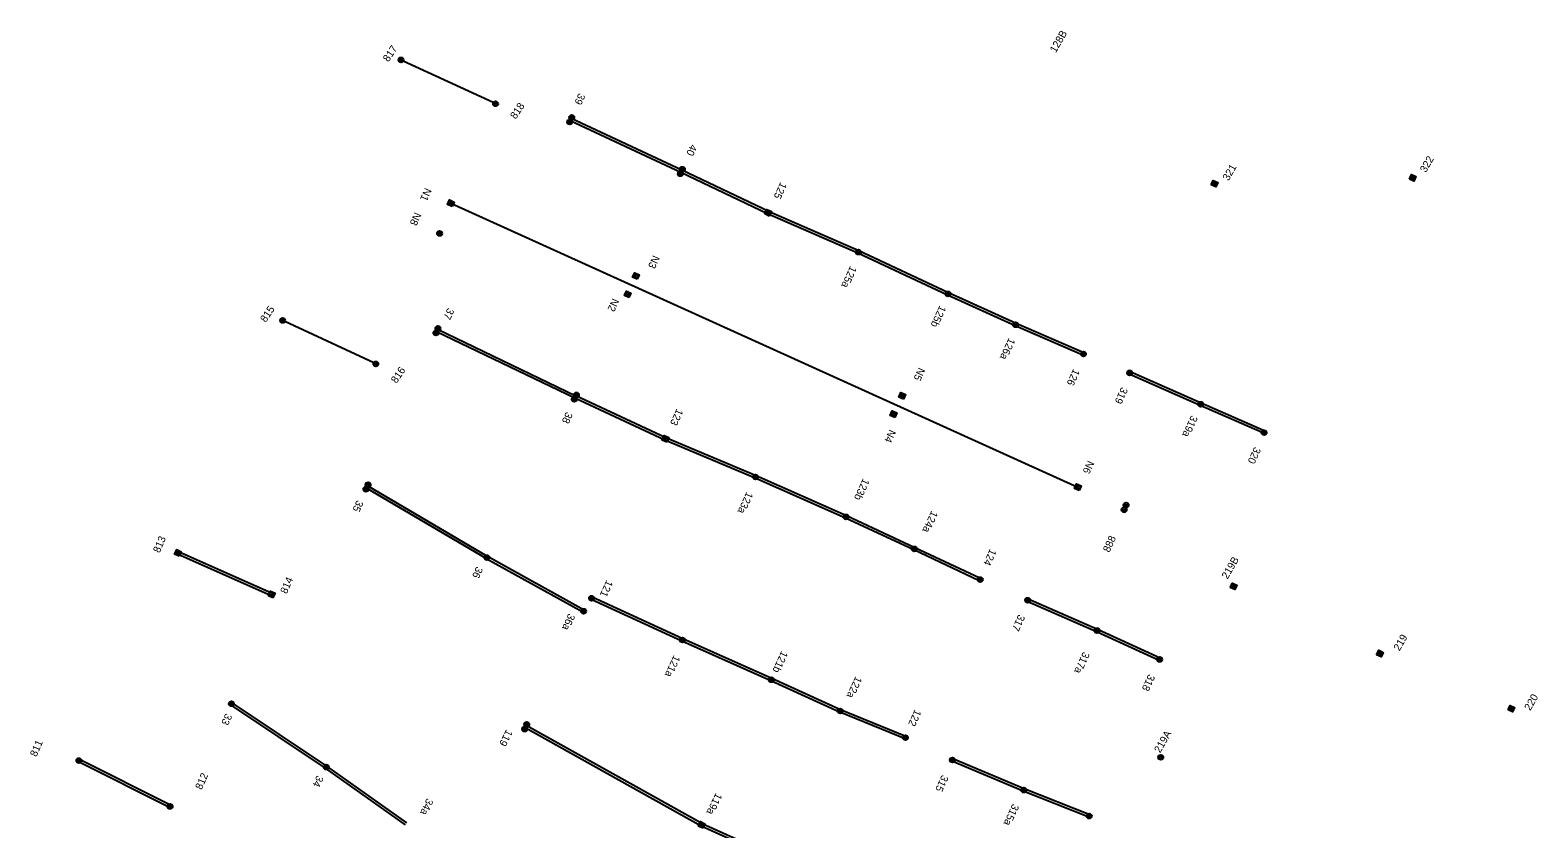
# Model space of a CAD drawing. Extents: x -595867 to -593796, y -1159595 to -1157495.
# Drawn here: x -595245.9 to -594943.7, y -1159060 to -1158899.8 of the extents above; entities that cross this region are included whole.
import ezdxf

# ---------------------------------------------------------------- set-up
doc = ezdxf.new("R2010")
doc.units = 0
for name, color, linetype in [('BVK_kanalizace_jednotna_nova', 7, 'Continuous'), ('DKM19', 7, 'Continuous'), ('SO31_06_54_1-protlak', 7, 'Continuous'), ('Vrstva 2', 7, 'Continuous'), ('Vrstva 7 návěstidla', 7, 'Continuous')]:
    doc.layers.add(name, color=color, linetype=linetype)

# ---------------------------------------------------------------- blocks, each defined once
blk = doc.blocks.new('C661_2')
at = {"layer": 'SO31_06_54_1-protlak'}
for p, q in [((-0.005, 0.0003), (-0.0003, 0.005)), ((-0.005, -0.005), (0.005, 0.005)), ((0.0003, -0.005), (0.005, -0.0003))]:
    blk.add_line(p, q, dxfattribs=at)
blk.add_lwpolyline([(-0.005, 0.005), (0.005, 0.005), (0.005, -0.005), (-0.005, -0.005)], close=True, dxfattribs=at)
blk.add_lwpolyline([(-0.005, 0.005), (0.005, 0.005), (0.005, -0.005), (-0.005, -0.005), (-0.005, 0.005)], dxfattribs=at)
blk = doc.blocks.new('C661')
at = {"layer": 'Vrstva 2'}
for p, q in [((-0.005, 0.0003), (-0.0003, 0.005)), ((-0.005, -0.005), (0.005, 0.005)), ((0.0003, -0.005), (0.005, -0.0003))]:
    blk.add_line(p, q, dxfattribs=at)
blk.add_lwpolyline([(-0.005, 0.005), (0.005, 0.005), (0.005, -0.005), (-0.005, -0.005)], close=True, dxfattribs=at)
blk.add_lwpolyline([(-0.005, 0.005), (0.005, 0.005), (0.005, -0.005), (-0.005, -0.005), (-0.005, 0.005)], dxfattribs=at)

msp = doc.modelspace()

# ---------------------------------------------------------------- linework, layer by layer
at = {"layer": 'BVK_kanalizace_jednotna_nova'}
for p, q in [((-595171.67, -1158906.23), (-595171.8, -1158905.33)), ((-595171.3, -1158906.18), (-595171.43, -1158905.27)), ((-595152.73, -1158915.04), (-595152.86, -1158914.14)), ((-595152.35, -1158914.99), (-595152.49, -1158914.08)), ((-595137.84, -1158918.69), (-595138, -1158917.79)), ((-595137.47, -1158918.64), (-595137.64, -1158917.72)), ((-595137.42, -1158917.78), (-595137.58, -1158916.88)), ((-595137.05, -1158917.73), (-595137.21, -1158916.81)), ((-595115.3, -1158929.02), (-595115.46, -1158928.11)), ((-595115.25, -1158928.16), (-595115.41, -1158927.26)), ((-595114.88, -1158928.1), (-595115.05, -1158927.19)), ((-595115.67, -1158929.08), (-595115.83, -1158928.18)), ((-595161.37, -1158934.05), (-595162, -1158934.28)), ((-595160.9, -1158934.27), (-595162.22, -1158934.76)), ((-595161.12, -1158934.75), (-595161.74, -1158934.98)), ((-595097.29, -1158936.17), (-595098.63, -1158936.63)), ((-595097.77, -1158935.94), (-595098.4, -1158936.16)), ((-595097.52, -1158936.65), (-595098.15, -1158936.86)), ((-595163.92, -1158941.03), (-595164.08, -1158940.13)), ((-595163.55, -1158940.97), (-595163.71, -1158940.06)), ((-595079.98, -1158944.79), (-595080.14, -1158943.89)), ((-595079.61, -1158944.73), (-595079.78, -1158943.82)), ((-595123.8, -1158948.86), (-595125.12, -1158949.34)), ((-595124.27, -1158948.64), (-595124.9, -1158948.86)), ((-595124.02, -1158949.34), (-595124.64, -1158949.57)), ((-595062.01, -1158953.16), (-595062.17, -1158952.26)), ((-595061.64, -1158953.1), (-595061.81, -1158952.19)), ((-595125.46, -1158952.51), (-595126.77, -1158953.03)), ((-595125.95, -1158952.3), (-595126.57, -1158952.55)), ((-595125.67, -1158953), (-595126.29, -1158953.24)), ((-595195.39, -1158958.49), (-595195.52, -1158957.59)), ((-595195.02, -1158958.44), (-595195.15, -1158957.53)), ((-595164.66, -1158961.01), (-595164.82, -1158960.11)), ((-595164.29, -1158960.95), (-595164.45, -1158960.04)), ((-595164.25, -1158960.09), (-595164.41, -1158959.19)), ((-595163.88, -1158960.03), (-595164.05, -1158959.12)), ((-595048.47, -1158959.36), (-595048.63, -1158958.46)), ((-595048.1, -1158959.3), (-595048.26, -1158958.39)), ((-595034.87, -1158965.22), (-595035.03, -1158964.32)), ((-595034.5, -1158965.17), (-595034.67, -1158964.25)), ((-595176.72, -1158967.21), (-595176.85, -1158966.31)), ((-595176.34, -1158967.16), (-595176.48, -1158966.25)), ((-595025.61, -1158969), (-595025.77, -1158968.1)), ((-595025.24, -1158968.95), (-595025.4, -1158968.03)), ((-595136.93, -1158974.31), (-595137.09, -1158973.42)), ((-595136.56, -1158974.26), (-595136.73, -1158973.34)), ((-595136.49, -1158973.41), (-595136.65, -1158972.51)), ((-595136.12, -1158973.35), (-595136.29, -1158972.44)), ((-595070.44, -1158972.86), (-595071.75, -1158973.38)), ((-595070.93, -1158972.65), (-595071.55, -1158972.9)), ((-595070.65, -1158973.35), (-595071.27, -1158973.59)), ((-595072.67, -1158976.33), (-595073.29, -1158976.58)), ((-595011.39, -1158975.29), (-595011.55, -1158974.39)), ((-595011.02, -1158975.23), (-595011.18, -1158974.32)), ((-595072.18, -1158976.54), (-595073.49, -1158977.06)), ((-595072.39, -1158977.03), (-595073.01, -1158977.27)), ((-595117.89, -1158981.5), (-595119.2, -1158982.02)), ((-595118.38, -1158981.29), (-595119, -1158981.54)), ((-595118.1, -1158981.99), (-595118.72, -1158982.23)), ((-594998.65, -1158980.99), (-594998.81, -1158980.09)), ((-594998.28, -1158980.93), (-594998.45, -1158980.02)), ((-595178.68, -1158992.34), (-595178.84, -1158991.44)), ((-595178.31, -1158992.28), (-595178.47, -1158991.37)), ((-595178.26, -1158991.43), (-595178.42, -1158990.53)), ((-595177.89, -1158991.37), (-595178.05, -1158990.46)), ((-595100.59, -1158989.88), (-595100.75, -1158988.98)), ((-595100.22, -1158989.82), (-595100.38, -1158988.91)), ((-595035.23, -1158991.19), (-595036.54, -1158991.71)), ((-595035.72, -1158990.98), (-595036.34, -1158991.23)), ((-595035.44, -1158991.68), (-595036.06, -1158991.92)), ((-595082.48, -1158997.88), (-595082.64, -1158996.98)), ((-595082.11, -1158997.82), (-595082.28, -1158996.91)), ((-595068.78, -1159004.29), (-595068.94, -1159003.39)), ((-595068.41, -1159004.23), (-595068.57, -1159003.32)), ((-595215.59, -1159004.39), (-595216.92, -1159004.86)), ((-595216.07, -1159004.16), (-595216.7, -1159004.38)), ((-595215.82, -1159004.86), (-595216.44, -1159005.08)), ((-595154.44, -1159006.04), (-595154.6, -1159005.14)), ((-595154.07, -1159005.98), (-595154.23, -1159005.07)), ((-595055.56, -1159010.46), (-595055.72, -1159009.56)), ((-595055.19, -1159010.4), (-595055.35, -1159009.49)), ((-595196.78, -1159012.74), (-595198.11, -1159013.21)), ((-595197.26, -1159012.51), (-595197.89, -1159012.73)), ((-595197.01, -1159013.21), (-595197.63, -1159013.44)), ((-595133.47, -1159014.2), (-595133.63, -1159013.3)), ((-595133.1, -1159014.15), (-595133.27, -1159013.23)), ((-595046.04, -1159014.59), (-595046.2, -1159013.69)), ((-595045.67, -1159014.53), (-595045.83, -1159013.62)), ((-595135.06, -1159016.79), (-595135.22, -1159015.89)), ((-595134.69, -1159016.73), (-595134.85, -1159015.82)), ((-595115.26, -1159022.57), (-595115.42, -1159021.67)), ((-595114.89, -1159022.51), (-595115.06, -1159021.6)), ((-595032.17, -1159020.69), (-595032.33, -1159019.79)), ((-595031.8, -1159020.64), (-595031.96, -1159019.72)), ((-595019.59, -1159026.46), (-595019.75, -1159025.56)), ((-595019.22, -1159026.4), (-595019.39, -1159025.49)), ((-595097.43, -1159030.55), (-595097.59, -1159029.65)), ((-595097.06, -1159030.5), (-595097.22, -1159029.58)), ((-595205.64, -1159035.35), (-595205.8, -1159034.45)), ((-595205.27, -1159035.29), (-595205.44, -1159034.38)), ((-595083.64, -1159036.8), (-595083.8, -1159035.9)), ((-595083.27, -1159036.75), (-595083.43, -1159035.83)), ((-595146.87, -1159040.43), (-595147.03, -1159039.53)), ((-595146.5, -1159040.38), (-595146.67, -1159039.46)), ((-595146.46, -1159039.52), (-595146.62, -1159038.62)), ((-595146.09, -1159039.46), (-595146.26, -1159038.55)), ((-595070.54, -1159042.15), (-595070.7, -1159041.25)), ((-595070.17, -1159042.09), (-595070.33, -1159041.18)), ((-595236.22, -1159046.75), (-595236.38, -1159045.85)), ((-595235.85, -1159046.7), (-595236.01, -1159045.78)), ((-595061.13, -1159046.64), (-595061.29, -1159045.74)), ((-595060.76, -1159046.58), (-595060.92, -1159045.67)), ((-595018.92, -1159045.97), (-595019.77, -1159045.63)), ((-595018.77, -1159045.63), (-595019.63, -1159045.28)), ((-595186.63, -1159048.06), (-595186.79, -1159047.16)), ((-595186.26, -1159048.01), (-595186.42, -1159047.09)), ((-595046.83, -1159052.66), (-595046.99, -1159051.76)), ((-595046.46, -1159052.6), (-595046.62, -1159051.69)), ((-595217.95, -1159055.94), (-595218.11, -1159055.04)), ((-595217.58, -1159055.89), (-595217.74, -1159054.97)), ((-595033.71, -1159057.89), (-595033.87, -1159056.99)), ((-595033.34, -1159057.83), (-595033.51, -1159056.92)), ((-595110.62, -1159058.93), (-595111.94, -1159059.41)), ((-595111.09, -1159058.71), (-595111.72, -1159058.93)), ((-595110.84, -1159059.41), (-595111.46, -1159059.64))]:
    msp.add_line(p, q, dxfattribs=at)
for points in [[(-595153.04, -1158914.29), (-595171.09, -1158905.99)], [(-595115.45, -1158928.36), (-595137.63, -1158917.98)], [(-595115.24, -1158927.9), (-595137.41, -1158917.52)], [(-595097.85, -1158936.18), (-595115.24, -1158927.9)], [(-595098.06, -1158936.63), (-595115.46, -1158928.35)], [(-595161.31, -1158935.17), (-595162.22, -1158934.75), (-595161.8, -1158933.85), (-595160.9, -1158934.27), (-595161.31, -1158935.17)], [(-595161.56, -1158934.51), (-595035.89, -1158991.45)], [(-595097.73, -1158937.07), (-595098.63, -1158936.63), (-595098.19, -1158935.73), (-595097.29, -1158936.17), (-595097.73, -1158937.07)], [(-595079.97, -1158944.54), (-595098.06, -1158936.63)], [(-595079.77, -1158944.08), (-595097.86, -1158936.17)], [(-595062.01, -1158952.91), (-595079.97, -1158944.54)], [(-595061.8, -1158952.45), (-595079.76, -1158944.08)], [(-595124.22, -1158949.76), (-595125.12, -1158949.34), (-595124.7, -1158948.44), (-595123.8, -1158948.86), (-595124.22, -1158949.76)], [(-595125.86, -1158953.43), (-595126.78, -1158953.03), (-595126.38, -1158952.11), (-595125.46, -1158952.51), (-595125.86, -1158953.43)], [(-595048.46, -1158959.11), (-595062, -1158952.91)], [(-595048.26, -1158958.65), (-595061.8, -1158952.45)], [(-595177.02, -1158966.51), (-595194.81, -1158958.23)], [(-595136.72, -1158973.6), (-595164.45, -1158960.29)], [(-595136.5, -1158973.16), (-595164.23, -1158959.84)], [(-595034.86, -1158964.97), (-595048.46, -1158959.11)], [(-595034.66, -1158964.51), (-595048.26, -1158958.65)], [(-595011.38, -1158975.04), (-595025.6, -1158968.75)], [(-595011.18, -1158974.58), (-595025.4, -1158968.29)], [(-595118.44, -1158981.53), (-595136.5, -1158973.15)], [(-595070.84, -1158973.78), (-595071.76, -1158973.38), (-595071.36, -1158972.46), (-595070.44, -1158972.86), (-595070.84, -1158973.78)], [(-595118.65, -1158981.99), (-595136.71, -1158973.61)], [(-595072.58, -1158977.46), (-595073.5, -1158977.06), (-595073.1, -1158976.14), (-595072.18, -1158976.54), (-595072.58, -1158977.46)], [(-594998.92, -1158980.49), (-595011.38, -1158975.04)], [(-594998.68, -1158980.05), (-595011.18, -1158974.58)], [(-595118.29, -1158982.42), (-595119.21, -1158982.02), (-595118.81, -1158981.1), (-595117.89, -1158981.5), (-595118.29, -1158982.42)], [(-595100.58, -1158989.63), (-595118.65, -1158981.99)], [(-595100.38, -1158989.17), (-595118.45, -1158981.53)], [(-595154.2, -1159005.34), (-595178.23, -1158991.18)], [(-595082.47, -1158997.63), (-595100.58, -1158989.63)], [(-595082.27, -1158997.17), (-595100.38, -1158989.17)], [(-595035.63, -1158992.11), (-595036.55, -1158991.71), (-595036.15, -1158990.79), (-595035.23, -1158991.19), (-595035.63, -1158992.11)], [(-595154.46, -1159005.77), (-595178.49, -1158991.61)], [(-595068.77, -1159004.04), (-595082.47, -1158997.63)], [(-595068.56, -1159003.58), (-595082.26, -1158997.17)], [(-595055.56, -1159009.72), (-595068.56, -1159003.58)], [(-595216.02, -1159005.29), (-595216.92, -1159004.86), (-595216.5, -1159003.95), (-595215.59, -1159004.38), (-595216.02, -1159005.29)], [(-595197.55, -1159013.2), (-595216.36, -1159004.85)], [(-595197.35, -1159012.74), (-595216.16, -1159004.39)], [(-595135.07, -1159016.53), (-595154.45, -1159005.78)], [(-595134.83, -1159016.09), (-595154.21, -1159005.34)], [(-595055.82, -1159010.17), (-595068.78, -1159004.04)], [(-595197.21, -1159013.64), (-595198.11, -1159013.21), (-595197.69, -1159012.3), (-595196.78, -1159012.73), (-595197.21, -1159013.64)], [(-595115.26, -1159022.32), (-595133.46, -1159013.95)], [(-595115.05, -1159021.86), (-595133.26, -1159013.49)], [(-595032.16, -1159020.44), (-595046.03, -1159014.34)], [(-595031.96, -1159019.98), (-595045.83, -1159013.88)], [(-595019.58, -1159026.21), (-595032.16, -1159020.44)], [(-595019.38, -1159025.75), (-595031.95, -1159019.98)], [(-595097.43, -1159030.3), (-595115.25, -1159022.32)], [(-595097.22, -1159029.84), (-595115.05, -1159021.86)], [(-595083.63, -1159036.55), (-595097.42, -1159030.3)], [(-595083.43, -1159036.09), (-595097.22, -1159029.84)], [(-595186.66, -1159047.79), (-595205.67, -1159035.08)], [(-595186.38, -1159047.37), (-595205.39, -1159034.66)], [(-595070.52, -1159041.9), (-595083.62, -1159036.55)], [(-595070.33, -1159041.44), (-595083.44, -1159036.09)], [(-595111.38, -1159059.41), (-595146.67, -1159039.7)], [(-595111.14, -1159058.97), (-595146.43, -1159039.26)], [(-595046.62, -1159051.95), (-595060.92, -1159045.93)], [(-595217.95, -1159055.68), (-595236.22, -1159046.49)], [(-595217.73, -1159055.24), (-595236, -1159046.05)], [(-595170.62, -1159059.18), (-595186.66, -1159047.78)], [(-595170.37, -1159058.78), (-595186.38, -1159047.38)], [(-595046.81, -1159052.41), (-595061.12, -1159046.39)], [(-595033.51, -1159057.18), (-595046.63, -1159051.95)], [(-595033.7, -1159057.64), (-595046.81, -1159052.41)], [(-595111.04, -1159059.83), (-595111.94, -1159059.41), (-595111.52, -1159058.51), (-595110.62, -1159058.93), (-595111.04, -1159059.83)], [(-595084.33, -1159071.65), (-595111.36, -1159059.42)], [(-595084.12, -1159071.19), (-595111.16, -1159058.96)]]:
    msp.add_lwpolyline(points, dxfattribs=at)
for points in [[(-595161.31, -1158935.17), (-595162.22, -1158934.75), (-595161.8, -1158933.85), (-595160.9, -1158934.27)], [(-595097.73, -1158937.07), (-595098.63, -1158936.63), (-595098.19, -1158935.73), (-595097.29, -1158936.17)], [(-595124.22, -1158949.76), (-595125.12, -1158949.34), (-595124.7, -1158948.44), (-595123.8, -1158948.86)], [(-595125.86, -1158953.43), (-595126.78, -1158953.03), (-595126.38, -1158952.11), (-595125.46, -1158952.51)], [(-595070.84, -1158973.78), (-595071.76, -1158973.38), (-595071.36, -1158972.46), (-595070.44, -1158972.86)], [(-595072.58, -1158977.46), (-595073.5, -1158977.06), (-595073.1, -1158976.14), (-595072.18, -1158976.54)], [(-595118.29, -1158982.42), (-595119.21, -1158982.02), (-595118.81, -1158981.1), (-595117.89, -1158981.5)], [(-595035.63, -1158992.11), (-595036.55, -1158991.71), (-595036.15, -1158990.79), (-595035.23, -1158991.19)], [(-595216.02, -1159005.29), (-595216.92, -1159004.86), (-595216.5, -1159003.95), (-595215.59, -1159004.38)], [(-595197.21, -1159013.64), (-595198.11, -1159013.21), (-595197.69, -1159012.3), (-595196.78, -1159012.73)], [(-595111.04, -1159059.83), (-595111.94, -1159059.41), (-595111.52, -1159058.51), (-595110.62, -1159058.93)]]:
    msp.add_lwpolyline(points, close=True, dxfattribs=at)
for centre in [(-595171.54, -1158905.75), (-595171.54, -1158905.75), (-595152.6, -1158914.56), (-595152.6, -1158914.56), (-595137.73, -1158918.21), (-595137.73, -1158918.21), (-595137.31, -1158917.3), (-595137.31, -1158917.3), (-595115.55, -1158928.59), (-595115.55, -1158928.59), (-595115.14, -1158927.68), (-595115.14, -1158927.68), (-595163.81, -1158940.55), (-595163.81, -1158940.55), (-595079.87, -1158944.31), (-595079.87, -1158944.31), (-595061.9, -1158952.68), (-595061.9, -1158952.68), (-595195.26, -1158958.01), (-595195.26, -1158958.01), (-595164.55, -1158960.53), (-595164.55, -1158960.53), (-595164.14, -1158959.61), (-595164.14, -1158959.61), (-595048.36, -1158958.88), (-595048.36, -1158958.88), (-595034.76, -1158964.74), (-595034.76, -1158964.74), (-595176.59, -1158966.73), (-595176.59, -1158966.73), (-595025.5, -1158968.52), (-595025.5, -1158968.52), (-595136.82, -1158973.83), (-595136.82, -1158973.83), (-595136.38, -1158972.93), (-595136.38, -1158972.93), (-595011.28, -1158974.81), (-595011.28, -1158974.81), (-594998.54, -1158980.51), (-594998.54, -1158980.51), (-595178.57, -1158991.86), (-595178.57, -1158991.86), (-595178.15, -1158990.95), (-595178.15, -1158990.95), (-595100.48, -1158989.4), (-595100.48, -1158989.4), (-595082.37, -1158997.4), (-595082.37, -1158997.4), (-595068.67, -1159003.81), (-595068.67, -1159003.81), (-595154.33, -1159005.56), (-595154.33, -1159005.56), (-595055.45, -1159009.98), (-595055.45, -1159009.98), (-595133.36, -1159013.72), (-595133.36, -1159013.72), (-595045.93, -1159014.11), (-595045.93, -1159014.11), (-595134.95, -1159016.31), (-595134.95, -1159016.31), (-595115.15, -1159022.09), (-595115.15, -1159022.09), (-595032.06, -1159020.21), (-595032.06, -1159020.21), (-595019.48, -1159025.98), (-595019.48, -1159025.98), (-595097.32, -1159030.07), (-595097.32, -1159030.07), (-595205.53, -1159034.87), (-595205.53, -1159034.87), (-595083.53, -1159036.32), (-595083.53, -1159036.32), (-595146.76, -1159039.95), (-595146.76, -1159039.95), (-595146.35, -1159039.03), (-595146.35, -1159039.03), (-595070.43, -1159041.67), (-595070.43, -1159041.67), (-595236.11, -1159046.27), (-595236.11, -1159046.27), (-595061.02, -1159046.16), (-595061.02, -1159046.16), (-595019.27, -1159045.62), (-595019.27, -1159045.62), (-595186.52, -1159047.58), (-595186.52, -1159047.58), (-595046.72, -1159052.18), (-595046.72, -1159052.18), (-595217.84, -1159055.46), (-595217.84, -1159055.46), (-595033.6, -1159057.41), (-595033.6, -1159057.41)]:
    msp.add_circle(centre, 0.5, dxfattribs=at)
at = {"layer": 'Vrstva 7 návěstidla'}
for p, q in [((-595026.09, -1158995.95), (-595027.1, -1158995.97)), ((-595027.1, -1158995.97), (-595026.09, -1158995.95)), ((-595026.99, -1158996.27), (-595026.69, -1158995.96)), ((-595025.7, -1158995.02), (-595026.7, -1158995.04)), ((-595026.7, -1158995.04), (-595025.7, -1158995.02)), ((-595026.65, -1158996.46), (-595026.16, -1158995.95)), ((-595026.59, -1158995.34), (-595026.3, -1158995.04)), ((-595026.25, -1158995.53), (-595025.77, -1158995.02))]:
    msp.add_line(p, q, dxfattribs=at)
for centre in [(-595026.2, -1158995.03), (-595026.6, -1158995.96)]:
    msp.add_circle(centre, 0.503, dxfattribs=at)
for centre in [(-595026.6, -1158995.96), (-595026.2, -1158995.03)]:
    msp.add_arc(centre, 0.503, 181.3065, 1.3065, dxfattribs=at)

# ---------------------------------------------------------------- block references
at = {"layer": 'Vrstva 2'}
for name, p, xscale, yscale, rotation in [('C661_2', (-595008.48, -1158930.58), 99.99959234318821, 99.99959234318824, 65.45078500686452), ('C661_2', (-594968.77, -1158929.4), 99.99959234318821, 99.99959234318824, 65.45078500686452), ('C661', (-595004.67, -1159011.33), 99.99967137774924, 99.99967137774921, 65.39359517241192), ('C661', (-594975.33, -1159024.82), 99.99967137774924, 99.99967137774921, 65.39359517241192), ('C661_2', (-594949, -1159035.86), 99.99967137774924, 99.99967137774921, 65.39359517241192)]:
    msp.add_blockref(name, p, dxfattribs=dict(at, xscale=xscale, yscale=yscale, rotation=rotation))

# ---------------------------------------------------------------- texts
at = {"layer": 'BVK_kanalizace_jednotna_nova'}
for s, rotation, p in [('817', 56, (-595174.06, -1158906.28)), ('818', 56, (-595148.56, -1158917.75)), ('815', 56, (-595198.66, -1158958.51)), ('816', 56, (-595172.45, -1158970.74)), ('813', 66.553, (-595219.95, -1159004.74)), ('814', 66.553, (-595194.46, -1159012.95)), ('811', 66.553, (-595244.62, -1159045.62)), ('812', 66.553, (-595211.49, -1159052.23))]:
    msp.add_text(s, height=1.5, rotation=rotation, dxfattribs=at).set_placement(p)
at = {"layer": 'DKM19'}
for s, rotation, p in [('128B', 60, (-595040.31, -1158904.44)), ('39', 245.4576, (-595135.9, -1158912.31)), ('40', 245.4576, (-595113.48, -1158922.55)), ('322', 60, (-594966.13, -1158928.48)), ('321', 60, (-595005.68, -1158930.12)), ('125', 245.024, (-595095.48, -1158930.18)), ('N1', 245.8093, (-595166.71, -1158931.31)), ('N8', 245.8093, (-595168.78, -1158936.2)), ('N3', 245.8093, (-595121.01, -1158944.83)), ('125a', 245.3226, (-595081.48, -1158946.99)), ('N2', 245.8093, (-595129.14, -1158953.46)), ('125b', 245.3692, (-595063.57, -1158954.9)), ('37', 245.8093, (-595162.18, -1158955.39)), ('126a', 245.3692, (-595049.71, -1158961.4)), ('N5', 245.4296, (-595067.78, -1158967.33)), ('126', 245.3692, (-595036.76, -1158967.61)), ('319', 245.3834, (-595027.15, -1158971.27)), ('38', 245.8093, (-595138.44, -1158976.24)), ('123', 245.2652, (-595116.26, -1158975.6)), ('319a', 245.3834, (-595013.14, -1158976.92)), ('N4', 245.4296, (-595073.65, -1158979.76)), ('320', 245.3834, (-595000.49, -1158983.27)), ('N6', 245.3863, (-595033.9, -1158985.98)), ('123b', 245.4296, (-595078.92, -1158989.59)), ('35', 245.8093, (-595180.39, -1158993.95)), ('123a', 245.3226, (-595102.25, -1158992.27)), ('124a', 245.3226, (-595065.21, -1158996.08)), ('888', 65.3834, (-595029.57, -1159004.64)), ('124', 245.4186, (-595053.47, -1159003.71)), ('219B', 60, (-595005.88, -1159009.99)), ('36', 245.8093, (-595156.42, -1159007.25)), ('121', 245.8093, (-595130.35, -1159009.98)), ('36a', 245.8093, (-595137.94, -1159016.67)), ('317', 245.4186, (-595047.75, -1159016.84)), ('219', 60, (-594971.42, -1159024.4)), ('121b', 245.3834, (-595095.27, -1159024.18)), ('317a', 245.3901, (-595034.8, -1159024.33)), ('121a', 245.3834, (-595116.86, -1159025.04)), ('122a', 245.3834, (-595080.42, -1159029.27)), ('318', 245.3901, (-595021.7, -1159028.85)), ('220', 60, (-594945.21, -1159036.37)), ('33', 245.2845, (-595206.68, -1159036.69)), ('122', 245.3834, (-595068.53, -1159035.91)), ('119', 243.3192, (-595150.42, -1159039.93)), ('219A', 60, (-595019.4, -1159044.86)), ('34', 245.2845, (-595188.37, -1159049.12)), ('315', 245.3834, (-595063.11, -1159049.05)), ('34a', 245.2845, (-595166.36, -1159053.73)), ('119a', 244.0149, (-595108.42, -1159052.65)), ('315a', 245.3834, (-595048.95, -1159054.84))]:
    msp.add_text(s, height=1.5, rotation=rotation, dxfattribs=at).set_placement(p)

doc.saveas('drawing.dxf')
